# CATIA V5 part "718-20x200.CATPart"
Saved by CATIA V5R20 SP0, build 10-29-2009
Part number: 718-20x200
Definition: NONE
Nomenclature: 718-20x200
Source: Unknown
Description: 718-20x200
Bounding box of the stored display mesh (mm): x 0 to 223, y -12.5 to 12.5, z -12.5 to 12.5
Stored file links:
  C:\Users\Utente\Desktop\IO LAVORO\3D X SITO CF\X SITO\718\718-20x200.CATPart

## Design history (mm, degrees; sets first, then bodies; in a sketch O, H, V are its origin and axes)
Body1 "718-20x200" (main body)
  Solid1: solid without history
